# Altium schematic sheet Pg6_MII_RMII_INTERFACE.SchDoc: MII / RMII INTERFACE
size 431 x 279 mm; Date: Not shown in title block; ApprovedBy: Not shown in title block; CheckedBy: Not shown in title block; Author: Not shown in title block; CompanyName: Not shown in title block; Engineer: Not shown in title block; Organization: Not shown in title block; Address1: Not shown in title block; Address2: Not shown in title block; Address3: Not shown in title block; Address4: Not shown in title block; DocumentNumber: 6; Revision: Use project parameter SCH_Rev; SheetNumber: 6; SheetTotal: 9; PageSetup: Record=PageOptions|CenterHorizontal=True|CenterVertical=True|PrintScale=1.00|XCorrection=1.00|YCorrection=1.00|PrintKind=0|BorderSize=5000000|LeftOffset=0|BottomOffset=0|Orientation=2|PaperLength=1000|PaperWidth=1000|Scale=100|PaperSource=15|PrintQuality=600|MediaType=1|DitherType=10|PaperKind=Letter|PrintScaleMode=1
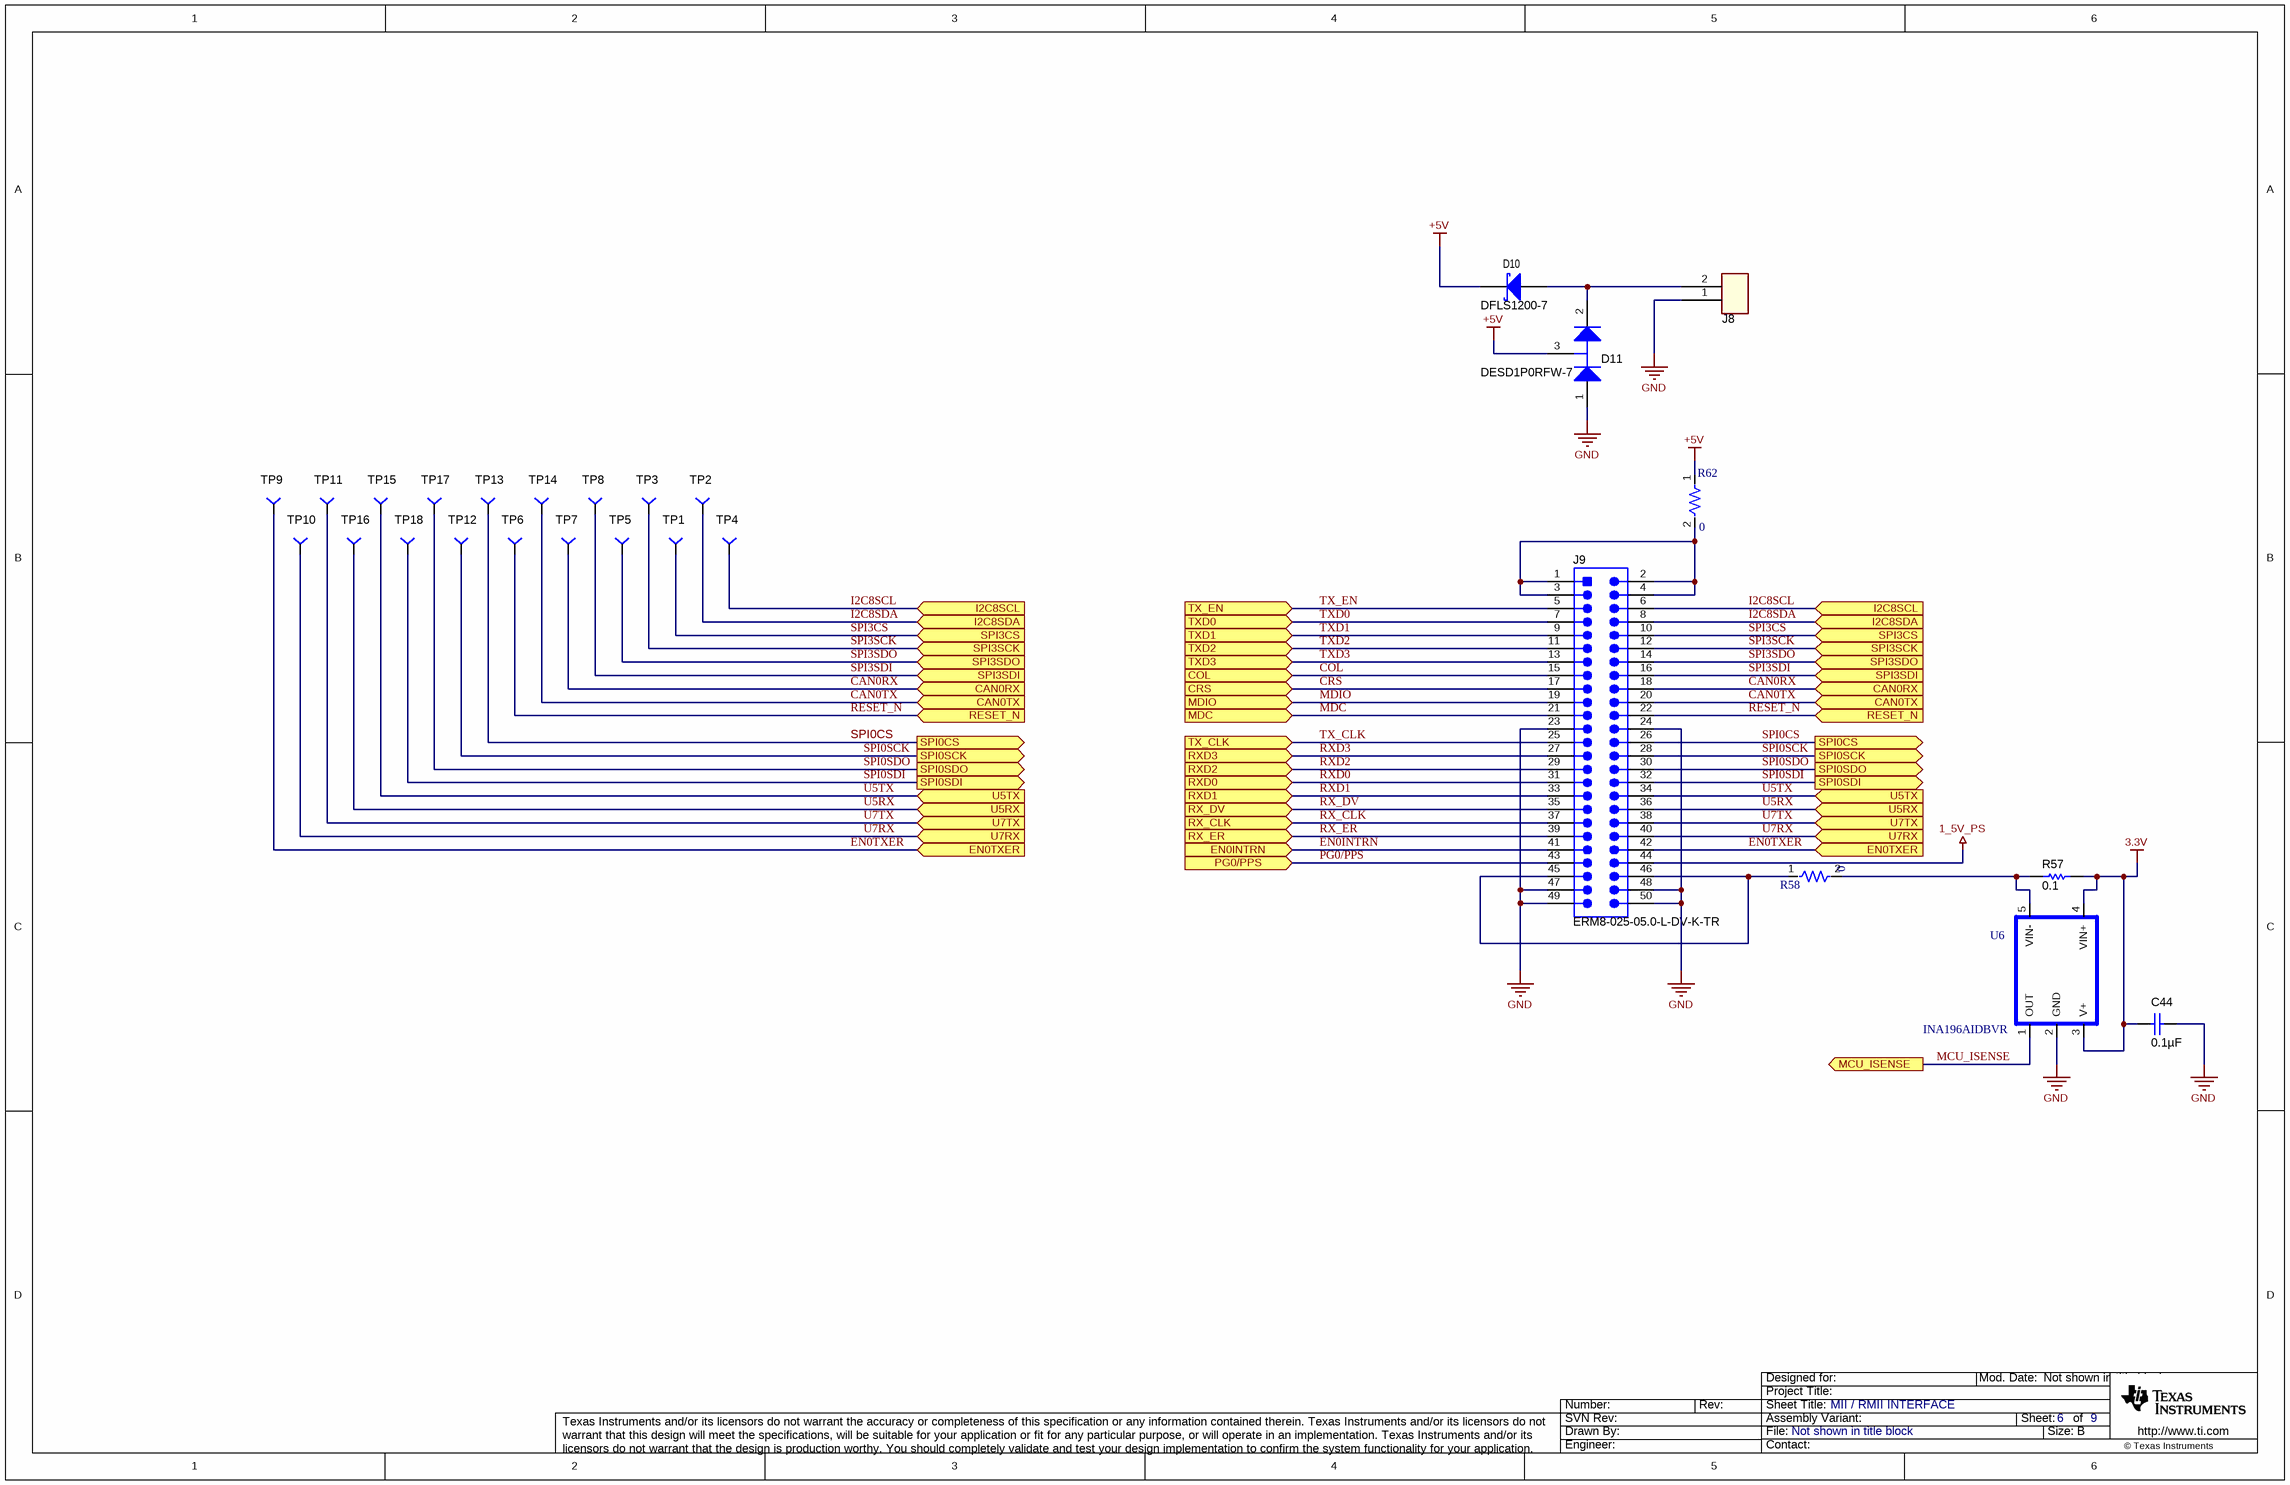
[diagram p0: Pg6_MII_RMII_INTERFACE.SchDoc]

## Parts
C44  ValueDisplayed: 0.1µF  [0603]  (hidden comment: 06033C104JAT2A)
D10  DFLS1200-7  [powerDI123]
D11  DESD1P0RFW-7  [SOT-323]
J8  CON-OSTVN02A150  [CN2_MTB_P100_PD80_D1.1_S5.54X6.5_STACK]  (value not drawn)
J9  ERM8-025-05.0-L-DV-K-TR  [SAMTEC_ERM8-025-05_0-L-DV-K-TR]
R57  value 0.1  [0603]  (hidden comment: ERJ-3RSFR10V)
R58  value 0  [0603]  (hidden comment: RESC0603)
R62  value 0  [0603]  (hidden comment: RESC0603)
TP1  TP1_PD40_D0.5_S50  [TP1_PD40_D0.5_S50]  (value not drawn)
TP2  TP1_PD40_D0.5_S50  [TP1_PD40_D0.5_S50]  (value not drawn)
TP3  TP1_PD40_D0.5_S50  [TP1_PD40_D0.5_S50]  (value not drawn)
TP4  TP1_PD40_D0.5_S50  [TP1_PD40_D0.5_S50]  (value not drawn)
TP5  TP1_PD40_D0.5_S50  [TP1_PD40_D0.5_S50]  (value not drawn)
TP6  TP1_PD40_D0.5_S50  [TP1_PD40_D0.5_S50]  (value not drawn)
TP7  TP1_PD40_D0.5_S50  [TP1_PD40_D0.5_S50]  (value not drawn)
TP8  TP1_PD40_D0.5_S50  [TP1_PD40_D0.5_S50]  (value not drawn)
TP9  TP1_PD40_D0.5_S50  [TP1_PD40_D0.5_S50]  (value not drawn)
TP10  TP1_PD40_D0.5_S50  [TP1_PD40_D0.5_S50]  (value not drawn)
TP11  TP1_PD40_D0.5_S50  [TP1_PD40_D0.5_S50]  (value not drawn)
TP12  TP1_PD40_D0.5_S50  [TP1_PD40_D0.5_S50]  (value not drawn)
TP13  TP1_PD40_D0.5_S50  [TP1_PD40_D0.5_S50]  (value not drawn)
TP14  TP1_PD40_D0.5_S50  [TP1_PD40_D0.5_S50]  (value not drawn)
TP15  TP1_PD40_D0.5_S50  [TP1_PD40_D0.5_S50]  (value not drawn)
TP16  TP1_PD40_D0.5_S50  [TP1_PD40_D0.5_S50]  (value not drawn)
TP17  TP1_PD40_D0.5_S50  [TP1_PD40_D0.5_S50]  (value not drawn)
TP18  TP1_PD40_D0.5_S50  [TP1_PD40_D0.5_S50]  (value not drawn)
U6  INA196AIDBVR  [SOT23-5P]

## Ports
CAN0RX, CAN0TX, COL, CRS, EN0INTRN, EN0TXER, I2C8SCL, I2C8SDA, MCU_ISENSE (out), MDC, MDIO, PG0/PPS, RESET_N, RX_CLK, RX_DV, RX_ER, RXD0, RXD1, RXD2, RXD3, SPI0CS, SPI0SCK, SPI0SDI, SPI0SDO, SPI3CS, SPI3SCK, SPI3SDI, SPI3SDO, TX_CLK, TX_EN, TXD0, TXD1, TXD2, TXD3, U5RX, U5TX, U7RX, U7TX

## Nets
1_5V_PS: J9.44
3.3V: C44.1 R57.2 U6.3(V+) U6.4(VIN+)
+5V: D10.1(K) D11.3(C) R62.1
GND: C44.2 D11.1(A) J8.1 J9.23 J9.24 J9.47 J9.48 J9.49 J9.50 U6.2(GND)
CAN0RX: J9.18 TP7.1 ; port CAN0RX
CAN0TX: J9.20 TP14.1 ; port CAN0TX
COL: J9.15 ; port COL
CRS: J9.17 ; port CRS
EN0INTRN: J9.41 ; port EN0INTRN
EN0TXER: J9.42 TP9.1 ; port EN0TXER
I2C8SCL: J9.6 TP4.1 ; port I2C8SCL
I2C8SDA: J9.8 TP2.1 ; port I2C8SDA
MCU_ISENSE: U6.1(OUT) ; port MCU_ISENSE
MDC: J9.21 ; port MDC
MDIO: J9.19 ; port MDIO
PG0/PPS: J9.43 ; port PG0/PPS
RESET_N: J9.22 TP6.1 ; port RESET_N
RX_CLK: J9.37 ; port RX_CLK
RX_DV: J9.35 ; port RX_DV
RX_ER: J9.39 ; port RX_ER
RXD0: J9.31 ; port RXD0
RXD1: J9.33 ; port RXD1
RXD2: J9.29 ; port RXD2
RXD3: J9.27 ; port RXD3
SPI0CS: J9.26 TP13.1 ; port SPI0CS
SPI0SCK: J9.28 TP12.1 ; port SPI0SCK
SPI0SDI: J9.32 TP18.1 ; port SPI0SDI
SPI0SDO: J9.30 TP17.1 ; port SPI0SDO
SPI3CS: J9.10 TP1.1 ; port SPI3CS
SPI3SCK: J9.12 TP3.1 ; port SPI3SCK
SPI3SDI: J9.16 TP8.1 ; port SPI3SDI
SPI3SDO: J9.14 TP5.1 ; port SPI3SDO
TX_CLK: J9.25 ; port TX_CLK
TX_EN: J9.5 ; port TX_EN
TXD0: J9.7 ; port TXD0
TXD1: J9.9 ; port TXD1
TXD2: J9.11 ; port TXD2
TXD3: J9.13 ; port TXD3
U5RX: J9.36 TP16.1 ; port U5RX
U5TX: J9.34 TP15.1 ; port U5TX
U7RX: J9.40 TP10.1 ; port U7RX
U7TX: J9.38 TP11.1 ; port U7TX
NetD10_2: D10.2(A) D11.2(K) J8.2
NetJ9_1: J9.1 J9.2 J9.3 J9.4 R62.2
NetJ9_45: J9.45 J9.46 R58.1
NetR57_1: R57.1 R58.2 U6.5(VIN-)

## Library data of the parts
C44 = 06033C104JAT2A: CAP, CERM, 0.1uF, 25V, +/-5%, X7R, 0603; Manufacturer: AVX; Polarized: N; CompType: Capacitor; U/M: EA; Cap_F: 0.0000001; Tolerance_%: 5; ESR_Ohm: 0.05; Value1: 0.05 ohm; VDC_V: 25; TaMin_C: -55; TaMax_C: 125
D10 = DFLS1200-7: Diode, Schottky, 200V, 1A, PowerDI123; Manufacturer: Diodes Inc.; U/M: EA; Vf_V: 0.85; Value2: 0.85V; Io_A: 1; Vr_V: 200; TJmax_C: 175; RJC_CperW: 7
D11 = BAV99WT1G: Diode, P-N, 70V, 0.2A, SOT-323; Manufacturer: Diodes Inc
J8 = CON-OSTVN02A150: Terminal Block, 4x1, 2.54mm, TH; Manufacturer: On Shore Technology Inc; SymbolCreator: x0120606
J9 = ERM8-025-05.0-L-DV-K-TR: CONN MICRO HS TERM STRP HDR 50 POS; Manufacturer: Samtec; SymbolCreator: a0799628; CompType: Header; U/M: EA
R57 = ERJ-3RSFR10V: RES, 0.1 ohm, 1%, 0.1W, 0603; Manufacturer: Panasonic; CompType: Resistor; Value_Code: R100; Tolerance_%: 1; TempCo: 300 ppm/C; EIA_Code: E96; U/M: EA
R58 R62 = RESC0603: Resistor, 0 OHM 1/10W 0603 SMD; Manufacturer #1: Generic; Part Number: ERJ-3GEY0R00V; PCB DECAL: RESC0603N; GNUM: G11-R0603-R000-AAA; Description: Resistor,Chip;1.60mm L X 0.83mm W X 0.60mm H; Geometry.Height: 0.6mm; PCBL.Component: CHP;RESC;1500;1700;150;400;700;950;600; PCBL.Process: F;N;50;50;200;100;200;250;350;-50;0; Tolerance: 5%
TP1-TP18 = TP-040_RND: Test Point 40mil pad 20mil drill; Manufacturer: STD; Description: Test Point, O.040 Hole; Value: STD
U6 = INA19NAIDBV: IC, Current Shunt Monitor, -16V to 80V Common-Mode Range; Manufacturer: TI; Alternate Manufacturer: None; Area: 23200; Value: INA196/8AIDBV; PCB DECAL: REF3230AIDBVT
